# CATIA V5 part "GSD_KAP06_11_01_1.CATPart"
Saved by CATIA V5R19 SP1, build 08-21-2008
Part number: GSD_BLEND_03
Definition: Beispielmodell für die Funktion Übergang / Blend.
Description: CATIA V5 Flächenmodellierung  Copyright (c) 2009 Maik Hertha IT Consultants
Bounding box of the stored display mesh (mm): x 9.925 to 49.234, y 0 to 39.794, z 0 to 65.132
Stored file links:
  \GSD_BUCH_UEBUNG\GSD_KAP06_11_01_1.CATPart
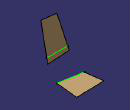
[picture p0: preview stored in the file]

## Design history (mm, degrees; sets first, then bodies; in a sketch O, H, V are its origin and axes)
AxisSystem1 "Absolute Axis System": origin (0, 0, 0), X (1, 0, 0), Y (0, 1, 0), Z (0, 0, 1)
Set1 "Planes.1"
  Plane1: type Equation, A 0, B 1, C 0, Length 0
  Plane2: type Equation, A 0, B 0, C 1, Length 0
  Plane3: type Equation, A 1, B 0, C 0, Length 0
Set2 "Skizzen.1"
  Sketch1 on Plane1, origin (0, 0, 0), H (-1, 0, 0), V (0, 0, 1)
    line L1 (-40.7892, 13.7277) -> (-49.2341, 65.1316)
    line L2 (-49.2341, 65.1316) -> (-29.5293, 63.051)
    line L3 (-29.5293, 63.051) -> (-14.1082, 15.4412)
    line L4 (-14.1082, 15.4412) -> (-40.7892, 13.7277)
  Sketch2 on Plane3, origin (0, 0, 0), H (0, 1, 0), V (0, 0, 1)
    line L1 (16.0881, 21.2572) -> (13.3955, 53.2011)
    line L2 (13.3955, 53.2011) -> (47.42, 60.6669)
    line L3 (47.42, 60.6669) -> (41.3005, 12.9347)
    line L4 (41.3005, 12.9347) -> (16.0881, 21.2572)
  Sketch3 on Plane2, origin (0, 0, 0), H (1, 0, 0), V (0, 1, 0)
    line L1 (12.7396, 17.2746) -> (9.9246, 38.9377)
    line L2 (9.9246, 38.9377) -> (44.561, 39.7944)
    line L3 (44.561, 39.7944) -> (41.746, 12.379)
    line L4 (41.746, 12.379) -> (12.7396, 17.2746)
Set3 "Basisflaechen.1"
  Split1: ToCut Plane1, Cutting Sketch1
  Split2: ToCut Plane3, Cutting Sketch2
  Split3: ToCut Plane2, Cutting Sketch3
Set4 "Blends"
  StIsoparamCurveFeature1 "CATStIsoparamCurveFeatureName": Support Split1, Direction {line type PtDir, Direction (1000, 0, 0), LENGTH 0, LENGTH 10, RefPoint {point type OnSurface, Support Split1, Direction (-0.0529, 0, -0.9986), Length 18.4178}}, Position {point type OnSurface, Support Split1, Direction (-0.0529, 0, -0.9986), Length 18.4178}
  Boundary1: Boundary edge of Split3
Body1 (main body)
